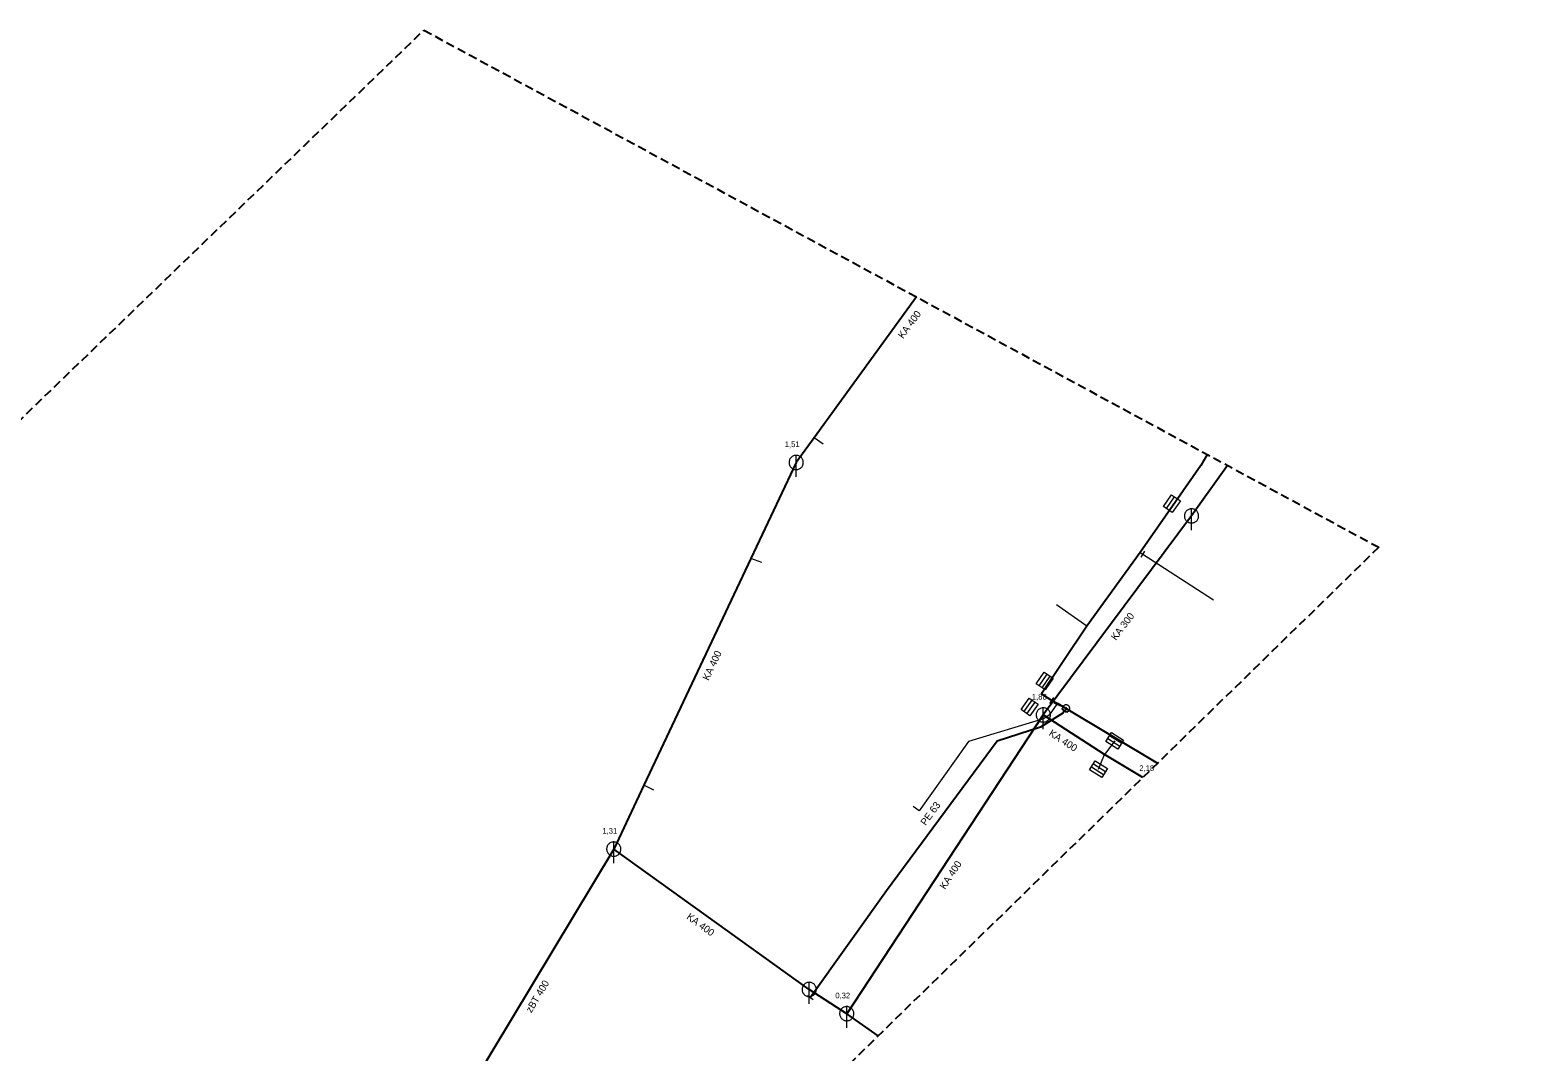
# Model space of a CAD drawing. Extents: x -724334 to -723692, y -972150 to -970648.
# Drawn here: x -723903.3 to -723691.8, y -970791.8 to -970648.4 of the extents above; entities that cross this region are included whole.
import ezdxf

# ---------------------------------------------------------------- set-up
doc = ezdxf.new("R2010")
doc.units = 0
doc.header["$LTSCALE"] = 0.4
doc.linetypes.add('MEDIUM_DASHED', pattern=[4.5, 3, -1.5])
for name, color, linetype, lineweight in [('1', 7, 'Continuous', 25), ('11', 7, 'Continuous', 13), ('13', 7, 'Continuous', 13), ('14', 7, 'Continuous', 25), ('17', 7, 'Continuous', 35), ('22', 7, 'Continuous', 13), ('34', 7, 'Continuous', 13), ('47', 7, 'Continuous', 13)]:
    doc.layers.add(name, color=color, linetype=linetype, lineweight=lineweight)

msp = doc.modelspace()

# ---------------------------------------------------------------- linework, layer by layer
at = {"layer": '1', "linetype": 'MEDIUM_DASHED'}
msp.add_lwpolyline([(-723848.074, -970648.428), (-723714.095, -970720.999), (-724065.788, -971064.318), (-723792.249, -971201.088), (-723702.93, -971508.122), (-723691.766, -972150.101), (-723842.491, -972097.068), (-723864.821, -971424.385), (-723982.052, -971259.703), (-724333.745, -971117.352)], close=True, dxfattribs=at)
at = {"layer": '11'}
for p, q in [((-723792.052, -970706.528), (-723793.305, -970705.613)), ((-723800.67, -970723.151), (-723802.182, -970722.551)), ((-723751.129, -970748.16), (-723752.592, -970750.072)), ((-723753.409, -970752.13), (-723752.592, -970750.072)), ((-723815.811, -970755.079), (-723817.193, -970754.361))]:
    msp.add_line(p, q, dxfattribs=at)
at = {"layer": '13'}
for p, q in [((-723747.21, -970721.949), (-723737.267, -970728.363)), ((-723755.061, -970732.084), (-723759.293, -970729.085))]:
    msp.add_line(p, q, dxfattribs=at)
msp.add_lwpolyline([(-723759.237, -970743.019), (-723760.346, -970744.574), (-723761.109, -970745.07), (-723771.64, -970748.259), (-723778.557, -970757.956), (-723779.416, -970757.353)], dxfattribs=at)
at = {"layer": '14'}
for p, q in [((-723735.321, -970709.502), (-723740.359, -970716.59)), ((-723740.359, -970716.59), (-723761.16, -970744.52)), ((-723821.43, -970763.34), (-723844.359, -970801.41)), ((-723784.313, -970789.545), (-723788.741, -970786.441))]:
    msp.add_line(p, q, dxfattribs=at)
at = {"layer": '14', "lineweight": 13}
for p, q in [((-723747.573, -970721.727), (-723747.21, -970721.949)), ((-723759.12, -970742.896), (-723759.237, -970743.019)), ((-723757.949, -970743.599), (-723758.16, -970743.93))]:
    msp.add_line(p, q, dxfattribs=at)
at = {"layer": '14'}
for points in [[(-723778.961, -970685.864), (-723793.305, -970705.613), (-723795.829, -970709.09)], [(-723795.829, -970709.09), (-723802.182, -970722.551), (-723817.193, -970754.361), (-723821.43, -970763.34)], [(-723761.16, -970744.52), (-723788.741, -970786.441), (-723794.003, -970783.038), (-723821.43, -970763.34)], [(-723747.194, -970753.31), (-723752.592, -970750.072), (-723761.16, -970744.52)]]:
    msp.add_lwpolyline(points, dxfattribs=at)
at = {"layer": '17', "lineweight": 25}
msp.add_line((-723757.949, -970743.599), (-723745.138, -970751.302), dxfattribs=at)
for points in [[(-723738.164, -970707.962), (-723739.045, -970709.525), (-723747.573, -970721.727), (-723755.061, -970732.084), (-723761.419, -970741.556), (-723759.961, -970742.498)], [(-723759.961, -970742.498), (-723759.12, -970742.896), (-723757.949, -970743.599)], [(-723758.16, -970743.93), (-723758.394, -970744.253), (-723761.572, -970746.219), (-723767.643, -970748.189), (-723783.137, -970769.203), (-723793.852, -970784.218)]]:
    msp.add_lwpolyline(points, dxfattribs=at)
at = {"layer": '22'}
for p, q in [((-723795.829, -970711.09), (-723795.828, -970708.09)), ((-723743.889, -970715.56), (-723742.743, -970713.921)), ((-723743.48, -970715.846), (-723742.333, -970714.208)), ((-723740.359, -970718.59), (-723740.358, -970715.59)), ((-723761.742, -970740.449), (-723760.613, -970738.798)), ((-723761.33, -970740.731), (-723760.2, -970739.081)), ((-723763.874, -970744.064), (-723762.713, -970742.435)), ((-723763.467, -970744.354), (-723762.306, -970742.726)), ((-723761.16, -970746.52), (-723761.159, -970743.52)), ((-723752.114, -970747.828), (-723750.42, -970748.891)), ((-723751.849, -970747.405), (-723750.154, -970748.468)), ((-723754.394, -970751.798), (-723752.7, -970752.861)), ((-723754.129, -970751.375), (-723752.434, -970752.438)), ((-723821.43, -970765.34), (-723821.429, -970762.34)), ((-723794.003, -970785.038), (-723794.002, -970782.038)), ((-723788.741, -970788.441), (-723788.74, -970785.441))]:
    msp.add_line(p, q, dxfattribs=at)
for points in [[(-723794.829, -970709.09), (-723794.834, -970708.981), (-723794.852, -970708.873), (-723794.882, -970708.767), (-723794.922, -970708.666), (-723794.974, -970708.569), (-723795.036, -970708.479), (-723795.108, -970708.396), (-723795.188, -970708.322), (-723795.276, -970708.256), (-723795.37, -970708.201), (-723795.47, -970708.156), (-723795.575, -970708.123), (-723795.682, -970708.101), (-723795.791, -970708.091), (-723795.901, -970708.093), (-723796.009, -970708.107), (-723796.116, -970708.132), (-723796.219, -970708.169), (-723796.317, -970708.218), (-723796.409, -970708.276), (-723796.495, -970708.345), (-723796.572, -970708.422), (-723796.641, -970708.508), (-723796.7, -970708.6), (-723796.748, -970708.698), (-723796.785, -970708.801), (-723796.811, -970708.908), (-723796.825, -970709.016), (-723796.828, -970709.126), (-723796.818, -970709.235), (-723796.797, -970709.342), (-723796.763, -970709.446), (-723796.719, -970709.546), (-723796.664, -970709.641), (-723796.598, -970709.729), (-723796.524, -970709.809), (-723796.441, -970709.881), (-723796.351, -970709.943), (-723796.255, -970709.995), (-723796.153, -970710.036), (-723796.048, -970710.066), (-723795.94, -970710.084), (-723795.83, -970710.09), (-723795.721, -970710.084), (-723795.613, -970710.066), (-723795.508, -970710.037), (-723795.406, -970709.996), (-723795.309, -970709.944), (-723795.219, -970709.882), (-723795.136, -970709.811), (-723795.061, -970709.731), (-723794.996, -970709.643), (-723794.94, -970709.549), (-723794.896, -970709.449), (-723794.862, -970709.345), (-723794.84, -970709.237), (-723794.83, -970709.128)], [(-723744.299, -970715.273), (-723743.152, -970713.634), (-723741.923, -970714.495), (-723743.07, -970716.133)], [(-723739.359, -970716.59), (-723739.364, -970716.481), (-723739.382, -970716.373), (-723739.412, -970716.267), (-723739.452, -970716.166), (-723739.504, -970716.069), (-723739.566, -970715.979), (-723739.638, -970715.896), (-723739.718, -970715.822), (-723739.806, -970715.756), (-723739.9, -970715.701), (-723740, -970715.656), (-723740.105, -970715.623), (-723740.212, -970715.601), (-723740.321, -970715.591), (-723740.431, -970715.593), (-723740.539, -970715.607), (-723740.646, -970715.632), (-723740.749, -970715.669), (-723740.847, -970715.718), (-723740.939, -970715.776), (-723741.025, -970715.845), (-723741.102, -970715.922), (-723741.171, -970716.008), (-723741.23, -970716.1), (-723741.278, -970716.198), (-723741.315, -970716.301), (-723741.341, -970716.408), (-723741.355, -970716.516), (-723741.358, -970716.626), (-723741.348, -970716.735), (-723741.327, -970716.842), (-723741.293, -970716.946), (-723741.249, -970717.046), (-723741.194, -970717.141), (-723741.128, -970717.229), (-723741.054, -970717.309), (-723740.971, -970717.381), (-723740.881, -970717.443), (-723740.785, -970717.495), (-723740.683, -970717.536), (-723740.578, -970717.566), (-723740.47, -970717.584), (-723740.36, -970717.59), (-723740.251, -970717.584), (-723740.143, -970717.566), (-723740.038, -970717.537), (-723739.936, -970717.496), (-723739.839, -970717.444), (-723739.749, -970717.382), (-723739.666, -970717.311), (-723739.591, -970717.231), (-723739.526, -970717.143), (-723739.47, -970717.049), (-723739.426, -970716.949), (-723739.392, -970716.845), (-723739.37, -970716.737), (-723739.36, -970716.628)], [(-723762.155, -970740.167), (-723761.025, -970738.516), (-723759.787, -970739.363), (-723760.917, -970741.014)], [(-723764.281, -970743.773), (-723763.12, -970742.145), (-723761.899, -970743.016), (-723763.06, -970744.644)], [(-723760.16, -970744.52), (-723760.165, -970744.411), (-723760.183, -970744.303), (-723760.213, -970744.197), (-723760.253, -970744.096), (-723760.305, -970743.999), (-723760.367, -970743.909), (-723760.439, -970743.826), (-723760.519, -970743.752), (-723760.607, -970743.686), (-723760.701, -970743.631), (-723760.801, -970743.586), (-723760.906, -970743.553), (-723761.013, -970743.531), (-723761.122, -970743.521), (-723761.232, -970743.523), (-723761.34, -970743.537), (-723761.447, -970743.562), (-723761.55, -970743.599), (-723761.648, -970743.648), (-723761.74, -970743.706), (-723761.826, -970743.775), (-723761.903, -970743.852), (-723761.972, -970743.938), (-723762.031, -970744.03), (-723762.079, -970744.128), (-723762.116, -970744.231), (-723762.142, -970744.338), (-723762.156, -970744.446), (-723762.159, -970744.556), (-723762.149, -970744.665), (-723762.128, -970744.772), (-723762.094, -970744.876), (-723762.05, -970744.976), (-723761.995, -970745.071), (-723761.929, -970745.159), (-723761.855, -970745.239), (-723761.772, -970745.311), (-723761.682, -970745.373), (-723761.586, -970745.425), (-723761.484, -970745.466), (-723761.379, -970745.496), (-723761.271, -970745.514), (-723761.161, -970745.52), (-723761.052, -970745.514), (-723760.944, -970745.496), (-723760.839, -970745.467), (-723760.737, -970745.426), (-723760.64, -970745.374), (-723760.55, -970745.312), (-723760.467, -970745.241), (-723760.392, -970745.161), (-723760.327, -970745.073), (-723760.271, -970744.979), (-723760.227, -970744.879), (-723760.193, -970744.775), (-723760.171, -970744.667), (-723760.161, -970744.558)], [(-723751.583, -970746.981), (-723749.889, -970748.044), (-723750.686, -970749.315), (-723752.38, -970748.252)], [(-723753.863, -970750.951), (-723752.169, -970752.014), (-723752.966, -970753.285), (-723754.66, -970752.222)], [(-723820.43, -970763.34), (-723820.435, -970763.231), (-723820.453, -970763.123), (-723820.483, -970763.017), (-723820.523, -970762.916), (-723820.575, -970762.819), (-723820.637, -970762.729), (-723820.709, -970762.646), (-723820.789, -970762.572), (-723820.877, -970762.506), (-723820.971, -970762.451), (-723821.071, -970762.406), (-723821.176, -970762.373), (-723821.283, -970762.351), (-723821.392, -970762.341), (-723821.502, -970762.343), (-723821.61, -970762.357), (-723821.717, -970762.382), (-723821.82, -970762.419), (-723821.918, -970762.468), (-723822.01, -970762.526), (-723822.096, -970762.595), (-723822.173, -970762.672), (-723822.242, -970762.758), (-723822.301, -970762.85), (-723822.349, -970762.948), (-723822.386, -970763.051), (-723822.412, -970763.158), (-723822.426, -970763.266), (-723822.429, -970763.376), (-723822.419, -970763.485), (-723822.398, -970763.592), (-723822.364, -970763.696), (-723822.32, -970763.796), (-723822.265, -970763.891), (-723822.199, -970763.979), (-723822.125, -970764.059), (-723822.042, -970764.131), (-723821.952, -970764.193), (-723821.856, -970764.245), (-723821.754, -970764.286), (-723821.649, -970764.316), (-723821.541, -970764.334), (-723821.431, -970764.34), (-723821.322, -970764.334), (-723821.214, -970764.316), (-723821.109, -970764.287), (-723821.007, -970764.246), (-723820.91, -970764.194), (-723820.82, -970764.132), (-723820.737, -970764.061), (-723820.662, -970763.981), (-723820.597, -970763.893), (-723820.541, -970763.799), (-723820.497, -970763.699), (-723820.463, -970763.595), (-723820.441, -970763.487), (-723820.431, -970763.378)], [(-723793.003, -970783.038), (-723793.008, -970782.929), (-723793.026, -970782.821), (-723793.056, -970782.715), (-723793.096, -970782.614), (-723793.148, -970782.517), (-723793.21, -970782.427), (-723793.282, -970782.344), (-723793.362, -970782.27), (-723793.45, -970782.204), (-723793.544, -970782.149), (-723793.644, -970782.104), (-723793.749, -970782.071), (-723793.856, -970782.049), (-723793.965, -970782.039), (-723794.075, -970782.041), (-723794.183, -970782.055), (-723794.29, -970782.08), (-723794.393, -970782.117), (-723794.491, -970782.166), (-723794.583, -970782.224), (-723794.669, -970782.293), (-723794.746, -970782.37), (-723794.815, -970782.456), (-723794.874, -970782.548), (-723794.922, -970782.646), (-723794.959, -970782.749), (-723794.985, -970782.856), (-723794.999, -970782.964), (-723795.002, -970783.074), (-723794.992, -970783.183), (-723794.971, -970783.29), (-723794.937, -970783.394), (-723794.893, -970783.494), (-723794.838, -970783.589), (-723794.772, -970783.677), (-723794.698, -970783.757), (-723794.615, -970783.829), (-723794.525, -970783.891), (-723794.429, -970783.943), (-723794.327, -970783.984), (-723794.222, -970784.014), (-723794.114, -970784.032), (-723794.004, -970784.038), (-723793.895, -970784.032), (-723793.787, -970784.014), (-723793.682, -970783.985), (-723793.58, -970783.944), (-723793.483, -970783.892), (-723793.393, -970783.83), (-723793.31, -970783.759), (-723793.235, -970783.679), (-723793.17, -970783.591), (-723793.114, -970783.497), (-723793.07, -970783.397), (-723793.036, -970783.293), (-723793.014, -970783.185), (-723793.004, -970783.076)], [(-723787.741, -970786.441), (-723787.746, -970786.332), (-723787.764, -970786.224), (-723787.794, -970786.118), (-723787.834, -970786.017), (-723787.886, -970785.92), (-723787.948, -970785.83), (-723788.02, -970785.747), (-723788.1, -970785.673), (-723788.188, -970785.607), (-723788.282, -970785.552), (-723788.382, -970785.507), (-723788.487, -970785.474), (-723788.594, -970785.452), (-723788.703, -970785.442), (-723788.813, -970785.444), (-723788.921, -970785.458), (-723789.028, -970785.483), (-723789.131, -970785.52), (-723789.229, -970785.569), (-723789.321, -970785.627), (-723789.407, -970785.696), (-723789.484, -970785.773), (-723789.553, -970785.859), (-723789.612, -970785.951), (-723789.66, -970786.049), (-723789.697, -970786.152), (-723789.723, -970786.259), (-723789.737, -970786.367), (-723789.74, -970786.477), (-723789.73, -970786.586), (-723789.709, -970786.693), (-723789.675, -970786.797), (-723789.631, -970786.897), (-723789.576, -970786.992), (-723789.51, -970787.08), (-723789.436, -970787.16), (-723789.353, -970787.232), (-723789.263, -970787.294), (-723789.167, -970787.346), (-723789.065, -970787.387), (-723788.96, -970787.417), (-723788.852, -970787.435), (-723788.742, -970787.441), (-723788.633, -970787.435), (-723788.525, -970787.417), (-723788.42, -970787.388), (-723788.318, -970787.347), (-723788.221, -970787.295), (-723788.131, -970787.233), (-723788.048, -970787.162), (-723787.973, -970787.082), (-723787.908, -970786.994), (-723787.852, -970786.9), (-723787.808, -970786.8), (-723787.774, -970786.696), (-723787.752, -970786.588), (-723787.742, -970786.479)]]:
    msp.add_lwpolyline(points, close=True, dxfattribs=at)
at = {"layer": '34'}
for p, q in [((-723746.939, -970721.528), (-723747.481, -970722.369)), ((-723760.246, -970742.908), (-723759.674, -970742.088)), ((-723759.689, -970742.806), (-723758.784, -970743.232)), ((-723757.725, -970744.177), (-723758.594, -970743.681)), ((-723793.444, -970784.508), (-723794.258, -970783.927))]:
    msp.add_line(p, q, dxfattribs=at)
at = {"layer": '47'}
for points in [[(-723757.52, -970743.856), (-723757.496, -970743.81), (-723757.476, -970743.761), (-723757.462, -970743.711), (-723757.452, -970743.66), (-723757.449, -970743.607), (-723757.451, -970743.555), (-723757.458, -970743.503), (-723757.471, -970743.453), (-723757.488, -970743.404), (-723757.511, -970743.356), (-723757.539, -970743.311), (-723757.572, -970743.271), (-723757.607, -970743.233), (-723757.648, -970743.199), (-723757.691, -970743.17), (-723757.737, -970743.146), (-723757.786, -970743.126), (-723757.837, -970743.112), (-723757.887, -970743.102), (-723757.94, -970743.099), (-723757.992, -970743.101), (-723758.044, -970743.108), (-723758.095, -970743.121), (-723758.144, -970743.138), (-723758.191, -970743.161), (-723758.236, -970743.189), (-723758.277, -970743.221), (-723758.314, -970743.257), (-723758.348, -970743.298), (-723758.377, -970743.341), (-723758.401, -970743.387), (-723758.421, -970743.436), (-723758.436, -970743.486), (-723758.445, -970743.537), (-723758.448, -970743.59), (-723758.447, -970743.642), (-723758.44, -970743.694), (-723758.427, -970743.745), (-723758.409, -970743.794), (-723758.386, -970743.841), (-723758.358, -970743.886), (-723758.327, -970743.927), (-723758.29, -970743.964), (-723758.249, -970743.998), (-723758.206, -970744.027), (-723758.16, -970744.051), (-723758.111, -970744.071), (-723758.062, -970744.086), (-723758.01, -970744.095), (-723757.957, -970744.098), (-723757.905, -970744.097), (-723757.854, -970744.089), (-723757.803, -970744.077), (-723757.754, -970744.059), (-723757.706, -970744.036), (-723757.661, -970744.008), (-723757.621, -970743.976), (-723757.583, -970743.94), (-723757.549, -970743.899)], [(-723757.878, -970743.641), (-723757.874, -970743.633), (-723757.871, -970743.625), (-723757.869, -970743.617), (-723757.867, -970743.609), (-723757.867, -970743.6), (-723757.867, -970743.591), (-723757.868, -970743.583), (-723757.87, -970743.575), (-723757.873, -970743.567), (-723757.877, -970743.559), (-723757.882, -970743.551), (-723757.887, -970743.545), (-723757.893, -970743.539), (-723757.899, -970743.533), (-723757.906, -970743.528), (-723757.914, -970743.524), (-723757.922, -970743.521), (-723757.93, -970743.519), (-723757.938, -970743.517), (-723757.947, -970743.517), (-723757.956, -970743.517), (-723757.964, -970743.518), (-723757.972, -970743.52), (-723757.981, -970743.523), (-723757.988, -970743.527), (-723757.996, -970743.532), (-723758.002, -970743.537), (-723758.008, -970743.543), (-723758.014, -970743.549), (-723758.019, -970743.556), (-723758.023, -970743.564), (-723758.026, -970743.572), (-723758.028, -970743.58), (-723758.03, -970743.588), (-723758.03, -970743.597), (-723758.031, -970743.605), (-723758.029, -970743.614), (-723758.027, -970743.622), (-723758.024, -970743.631), (-723758.02, -970743.638), (-723758.015, -970743.646), (-723758.01, -970743.652), (-723758.004, -970743.658), (-723757.998, -970743.664), (-723757.991, -970743.669), (-723757.983, -970743.673), (-723757.975, -970743.676), (-723757.967, -970743.678), (-723757.959, -970743.68), (-723757.95, -970743.68), (-723757.942, -970743.681), (-723757.933, -970743.679), (-723757.925, -970743.677), (-723757.917, -970743.674), (-723757.909, -970743.67), (-723757.901, -970743.665), (-723757.895, -970743.66), (-723757.889, -970743.654), (-723757.883, -970743.648)]]:
    msp.add_lwpolyline(points, close=True, dxfattribs=at)

# ---------------------------------------------------------------- texts
at = {"layer": '1'}
for s, rotation, p in [('KA 400', 54, (-723780.821, -970691.803)), ('KA 300', 53, (-723750.958, -970734.146)), ('KA 400', 65, (-723808.114, -970739.774)), ('KA 400', 327, (-723760.473, -970747.33)), ('PE 63 ', 54, (-723777.666, -970760.123)), ('KA 400', 57, (-723774.941, -970769.078)), ('KA 400', 324, (-723811.311, -970773.051)), ('zBT 400 ', 59, (-723832.999, -970786.397))]:
    msp.add_text(s, height=1, rotation=rotation, dxfattribs=at).set_placement(p)
for s, p in [('1,51', (-723797.43, -970706.937)), ('1,88', (-723762.76, -970742.367)), ('2,18', (-723747.687, -970752.39)), ('1,31', (-723823.029, -970761.187)), ('0,32', (-723790.341, -970784.289))]:
    msp.add_text(s, height=0.8, dxfattribs=at).set_placement(p)

doc.saveas('drawing.dxf')
